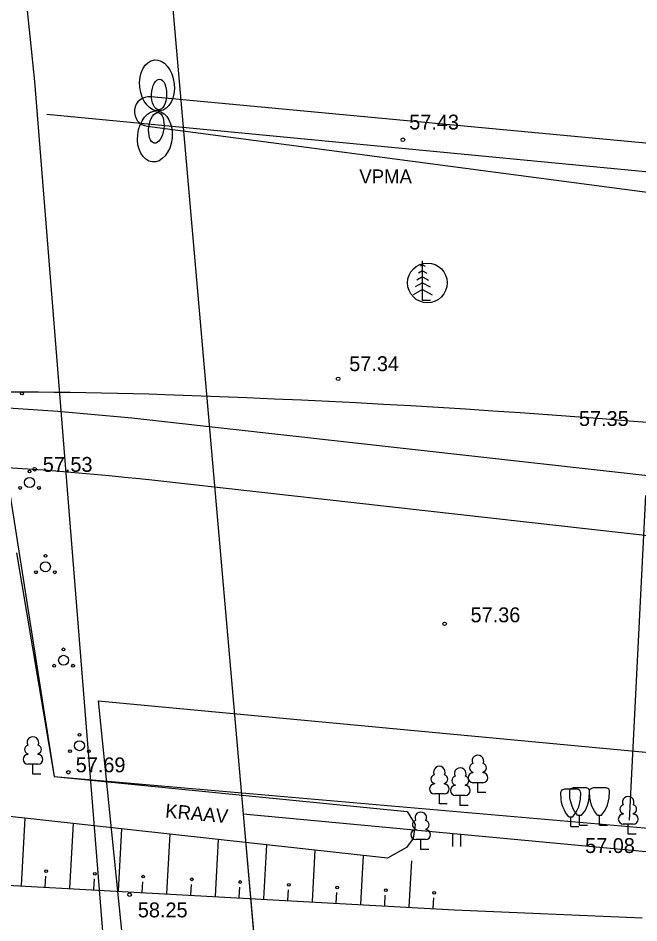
# Model space of a CAD drawing. Extents: x 9156 to 9809, y 2728 to 4000.
# Drawn here: x 9316.8 to 9348.14, y 3691.69 to 3737.31 of the extents above; entities that cross this region are included whole.
import ezdxf

# ---------------------------------------------------------------- set-up
doc = ezdxf.new("R2010")
doc.units = 0
for name, color, linetype in [('Level 1', 7, 'Continuous'), ('Level 11', 7, 'Continuous'), ('Level 16', 7, 'Continuous'), ('Level 17', 7, 'Continuous'), ('Level 18', 7, 'Continuous'), ('Level 21', 7, 'Continuous'), ('Level 54', 7, 'Continuous'), ('Level 56', 7, 'Continuous'), ('Level 6', 7, 'Continuous'), ('Level 7', 7, 'Continuous'), ('Level 8', 7, 'Continuous')]:
    doc.layers.add(name, color=color, linetype=linetype)

msp = doc.modelspace()

# ---------------------------------------------------------------- linework, layer by layer
at = {"layer": 'Level 1'}
for p, q in [((9317.65, 3734.12), (9308.72, 3821.62)), ((9317.65, 3734.12), (9308.72, 3821.62)), ((9347.38, 3362.85), (9317.65, 3734.12)), ((9347.38, 3362.85), (9317.65, 3734.12))]:
    msp.add_line(p, q, dxfattribs=at)
at = {"layer": 'Level 11'}
for points in [[(9328.17, 3697.177), (9337.927, 3586.83), (9359.389, 3586.857), (9356.831, 3657.924), (9386.375, 3658.386), (9385.932, 3691.773)], [(9328.17, 3697.177), (9337.927, 3586.771), (9359.389, 3586.857), (9356.831, 3657.924), (9386.375, 3658.386), (9385.932, 3691.773)]]:
    msp.add_lwpolyline(points, close=True, dxfattribs=at)
at = {"layer": 'Level 16'}
msp.add_line((9318.263, 3732.461), (9362.512, 3728.231), dxfattribs=at)
at = {"layer": 'Level 17'}
for p, q in [((9403.99, 3708.025), (9324.042, 3716.972)), ((9430.183, 3702.075), (9323.709, 3713.991))]:
    msp.add_line(p, q, dxfattribs=at)
for radius, end in [(153, 92.61532), (150, 93.06688)]:
    msp.add_arc((9307.025, 3564.922), radius, 83.61424, end, dxfattribs=at)
at = {"layer": 'Level 18'}
for p, q in [((9486.214, 3718.077), (9323.495, 3733.347)), ((9323.327, 3731.857), (9363.168, 3726.601))]:
    msp.add_line(p, q, dxfattribs=at)
for centre, radius, start, end in [((9323.425, 3732.6), 0.75, 84.6388, 262.4851), ((9316.067, 3469.7), 248.75, 88.12497, 94.00034), ((9307.887, 3219.834), 498.75, 83.04692, 88.12497)]:
    msp.add_arc(centre, radius, start, end, dxfattribs=at)
at = {"layer": 'Level 21'}
msp.add_circle((9337.461, 3723.96), 1, dxfattribs=at)
at = {"layer": 'Level 54'}
for p, q in [((9312.645, 3737.011), (9318.631, 3699.076)), ((9337.219, 3724.87), (9337.093, 3724.8)), ((9337.219, 3723.07), (9337.219, 3725.07)), ((9337.219, 3724.87), (9337.345, 3724.8)), ((9337.219, 3724.27), (9336.921, 3724.105)), ((9337.219, 3724.57), (9337.007, 3724.453)), ((9337.219, 3724.57), (9337.431, 3724.453)), ((9337.219, 3724.27), (9337.517, 3724.105)), ((9337.219, 3723.97), (9336.835, 3723.757)), ((9337.219, 3723.97), (9337.603, 3723.757)), ((9337.219, 3723.62), (9336.743, 3723.356)), ((9337.219, 3723.62), (9337.694, 3723.356)), ((9337.619, 3723.07), (9337.219, 3723.07)), ((9347.659, 3696.87), (9348.477, 3713.238)), ((9316.73, 3710.352), (9318.631, 3699.076)), ((9317.304, 3700.219), (9317.304, 3700.187)), ((9317.804, 3700.219), (9317.804, 3700.187)), ((9317.804, 3699.687), (9317.304, 3699.687)), ((9317.554, 3699.187), (9317.554, 3699.687)), ((9317.954, 3699.187), (9317.554, 3699.187)), ((9339.762, 3699.291), (9339.762, 3699.259)), ((9340.262, 3699.291), (9340.262, 3699.259)), ((9318.631, 3699.076), (9336.447, 3697.307)), ((9318.631, 3699.076), (9385.668, 3693.253)), ((9337.813, 3698.726), (9337.813, 3698.694)), ((9338.313, 3698.726), (9338.313, 3698.694)), ((9338.87, 3698.648), (9338.87, 3698.616)), ((9339.37, 3698.648), (9339.37, 3698.616)), ((9340.262, 3698.759), (9339.762, 3698.759)), ((9340.012, 3698.259), (9340.012, 3698.759)), ((9338.313, 3698.194), (9337.813, 3698.194)), ((9338.063, 3697.694), (9338.063, 3698.194)), ((9340.412, 3698.259), (9340.012, 3698.259)), ((9344.396, 3698.444), (9344.996, 3698.444)), ((9344.842, 3698.518), (9345.442, 3698.518)), ((9345.846, 3698.518), (9346.446, 3698.518)), ((9339.37, 3698.116), (9338.87, 3698.116)), ((9339.12, 3697.616), (9339.12, 3698.116)), ((9335.451, 3694.95), (9314.021, 3697.322)), ((9336.447, 3697.307), (9336.851, 3696.646)), ((9338.463, 3697.694), (9338.063, 3697.694)), ((9339.52, 3697.616), (9339.12, 3697.616)), ((9317.141, 3696.977), (9316.953, 3693.583)), ((9344.596, 3697.044), (9344.796, 3697.044)), ((9344.696, 3696.544), (9344.696, 3697.044)), ((9345.042, 3697.118), (9345.242, 3697.118)), ((9345.142, 3696.618), (9345.142, 3697.118)), ((9346.046, 3697.118), (9346.246, 3697.118)), ((9346.146, 3696.618), (9346.146, 3697.118)), ((9347.346, 3697.203), (9347.346, 3697.171)), ((9347.846, 3697.203), (9347.846, 3697.171)), ((9319.581, 3696.707), (9319.4, 3693.447)), ((9322.021, 3696.437), (9321.848, 3693.311)), ((9336.851, 3696.646), (9336.74, 3695.938)), ((9336.875, 3696.421), (9336.875, 3696.389)), ((9337.375, 3696.421), (9337.375, 3696.389)), ((9344.696, 3696.544), (9345.096, 3696.544)), ((9345.142, 3696.618), (9345.542, 3696.618)), ((9346.146, 3696.618), (9346.546, 3696.618)), ((9347.846, 3696.671), (9347.346, 3696.671)), ((9347.596, 3696.171), (9347.596, 3696.671)), ((9324.461, 3696.167), (9324.295, 3693.175)), ((9336.74, 3695.938), (9336.405, 3695.491)), ((9338.729, 3696.163), (9338.729, 3695.543)), ((9339.135, 3696.152), (9339.135, 3695.543)), ((9347.996, 3696.171), (9347.596, 3696.171)), ((9326.901, 3695.897), (9326.742, 3693.039)), ((9329.341, 3695.626), (9329.19, 3692.904)), ((9336.405, 3695.491), (9335.451, 3694.95)), ((9337.375, 3695.889), (9336.875, 3695.889)), ((9337.125, 3695.389), (9337.125, 3695.889)), ((9331.781, 3695.356), (9331.637, 3692.768)), ((9334.221, 3695.086), (9334.084, 3692.632)), ((9337.525, 3695.389), (9337.125, 3695.389)), ((9336.661, 3694.816), (9336.532, 3692.496)), ((9318.177, 3693.515), (9318.206, 3694.04)), ((9320.624, 3693.379), (9320.653, 3693.904)), ((9323.071, 3693.243), (9323.1, 3693.768)), ((9325.519, 3693.107), (9325.548, 3693.632)), ((9327.966, 3692.971), (9327.995, 3693.496)), ((9330.413, 3692.836), (9330.443, 3693.361)), ((9332.861, 3692.7), (9332.89, 3693.225)), ((9335.308, 3692.564), (9335.337, 3693.089)), ((9337.756, 3692.428), (9337.785, 3692.953)), ((9338.834, 3692.345), (9348.3, 3691.946))]:
    msp.add_line(p, q, dxfattribs=at)
for points in [[(9295.071, 3750), (9300.327, 3695.705), (9300.595, 3694.735), (9301.563, 3694.411), (9315.023, 3693.667), (9338.834, 3692.345)], [(9344.596, 3697.044), (9344.438, 3697.256), (9344.373, 3697.368), (9344.296, 3697.544), (9344.235, 3697.769), (9344.211, 3697.925), (9344.196, 3698.244), (9344.198, 3698.285), (9344.228, 3698.357), (9344.268, 3698.394), (9344.396, 3698.444)], [(9345.042, 3697.118), (9344.884, 3697.331), (9344.819, 3697.443), (9344.742, 3697.618), (9344.681, 3697.843), (9344.657, 3697.999), (9344.642, 3698.318), (9344.644, 3698.36), (9344.674, 3698.431), (9344.714, 3698.468), (9344.842, 3698.518)], [(9344.796, 3697.044), (9344.955, 3697.256), (9345.019, 3697.368), (9345.096, 3697.544), (9345.157, 3697.769), (9345.181, 3697.925), (9345.196, 3698.244), (9345.194, 3698.285), (9345.165, 3698.357), (9345.124, 3698.394), (9344.996, 3698.444)], [(9345.242, 3697.118), (9345.401, 3697.331), (9345.465, 3697.443), (9345.542, 3697.618), (9345.604, 3697.843), (9345.627, 3697.999), (9345.642, 3698.318), (9345.64, 3698.36), (9345.611, 3698.431), (9345.57, 3698.468), (9345.442, 3698.518)], [(9346.046, 3697.118), (9345.888, 3697.331), (9345.823, 3697.443), (9345.746, 3697.618), (9345.685, 3697.843), (9345.661, 3697.999), (9345.646, 3698.318), (9345.648, 3698.36), (9345.678, 3698.431), (9345.718, 3698.468), (9345.846, 3698.518)], [(9346.246, 3697.118), (9346.405, 3697.331), (9346.469, 3697.443), (9346.546, 3697.618), (9346.607, 3697.843), (9346.631, 3697.999), (9346.646, 3698.318), (9346.644, 3698.36), (9346.615, 3698.431), (9346.574, 3698.468), (9346.446, 3698.518)]]:
    msp.add_lwpolyline(points, dxfattribs=at)
for centre, radius in [((9336.225, 3731.179), 0.0909), ((9332.955, 3719.124), 0.0909), ((9316.999, 3718.389), 0.0707), ((9317.638, 3714.563), 0.0909), ((9317.382, 3714.446), 0.0707), ((9317.382, 3713.896), 0.25), ((9316.906, 3713.621), 0.0707), ((9317.858, 3713.621), 0.0707), ((9318.184, 3710.194), 0.0707), ((9318.184, 3709.644), 0.25), ((9317.708, 3709.369), 0.0707), ((9318.66, 3709.369), 0.0707), ((9338.332, 3706.771), 0.0909), ((9319.1, 3705.483), 0.0707), ((9319.1, 3704.933), 0.25), ((9318.624, 3704.658), 0.0707), ((9319.577, 3704.658), 0.0707), ((9319.902, 3701.174), 0.0707), ((9319.902, 3700.624), 0.25), ((9319.426, 3700.349), 0.0707), ((9320.379, 3700.349), 0.0707), ((9319.339, 3699.284), 0.0909), ((9318.227, 3694.295), 0.0683), ((9320.675, 3694.159), 0.0683), ((9323.122, 3694.023), 0.0683), ((9325.569, 3693.887), 0.0683), ((9328.017, 3693.751), 0.0683), ((9330.464, 3693.615), 0.0683), ((9322.429, 3693.113), 0.0909), ((9332.912, 3693.479), 0.0683), ((9335.359, 3693.344), 0.0683), ((9337.806, 3693.208), 0.0683)]:
    msp.add_circle(centre, radius, dxfattribs=at)
for centre, radius, start, end in [((9317.554, 3700.787), 0.292, 332.5799, 207.4201), ((9317.354, 3700.437), 0.224, 105.2441, 257.079), ((9317.754, 3700.437), 0.224, 282.921, 74.7559), ((9317.304, 3699.937), 0.25, 90, 270), ((9317.804, 3699.937), 0.25, 270, 90), ((9340.012, 3699.859), 0.292, 332.5799, 207.4201), ((9338.063, 3699.294), 0.292, 332.5799, 207.4201), ((9339.812, 3699.509), 0.224, 105.2441, 257.079), ((9340.212, 3699.509), 0.224, 282.921, 74.7559), ((9337.863, 3698.944), 0.224, 105.2441, 257.079), ((9338.263, 3698.944), 0.224, 282.921, 74.7559), ((9339.12, 3699.216), 0.292, 332.5799, 207.4201), ((9339.762, 3699.009), 0.25, 90, 270), ((9340.262, 3699.009), 0.25, 270, 90), ((9337.813, 3698.444), 0.25, 90, 270), ((9338.313, 3698.444), 0.25, 270, 90), ((9338.92, 3698.866), 0.224, 105.2441, 257.079), ((9339.32, 3698.866), 0.224, 282.921, 74.7559), ((9338.87, 3698.366), 0.25, 90, 270), ((9339.37, 3698.366), 0.25, 270, 90), ((9347.596, 3697.771), 0.292, 332.5799, 207.4201), ((9337.125, 3696.989), 0.292, 332.5799, 207.4201), ((9347.396, 3697.421), 0.224, 105.2441, 257.079), ((9347.796, 3697.421), 0.224, 282.921, 74.7559), ((9336.925, 3696.639), 0.224, 105.2441, 257.079), ((9337.325, 3696.639), 0.224, 282.921, 74.7559), ((9347.346, 3696.921), 0.25, 90, 270), ((9347.846, 3696.921), 0.25, 270, 90), ((9336.875, 3696.139), 0.25, 90, 270), ((9337.375, 3696.139), 0.25, 270, 90)]:
    msp.add_arc(centre, radius, start, end, dxfattribs=at)
at = {"layer": 'Level 56'}
for p, q in [((9486.214, 3718.077), (9323.495, 3733.347)), ((9323.327, 3731.857), (9363.168, 3726.601)), ((9403.99, 3708.025), (9324.042, 3716.972)), ((9430.183, 3702.075), (9323.709, 3713.991))]:
    msp.add_line(p, q, dxfattribs=at)
for centre, radius, start, end in [((9323.425, 3732.6), 0.75, 84.6388, 262.4851), ((9316.067, 3469.7), 248.75, 88.12497, 94.00034), ((9307.887, 3219.834), 498.75, 83.04692, 88.12497), ((9307.025, 3564.922), 153, 83.61424, 92.61532), ((9307.025, 3564.922), 150, 83.61424, 93.06688)]:
    msp.add_arc(centre, radius, start, end, dxfattribs=at)
at = {"layer": 'Level 6'}
msp.add_line((9306.372, 3945.862), (9356.727, 3371.389), dxfattribs=at)
at = {"layer": 'Level 7'}
for q in [(9322.45, 3687.11), (9474.788, 3688.481)]:
    msp.add_line((9320.839, 3702.885), q, dxfattribs=at)
at = {"layer": 'Level 8'}
for centre, major_axis, ratio in [((9323.814, 3733.915), (0.134, -1.286), 0.674652), ((9323.814, 3733.915), (0.134, -1.286), 0.674652), ((9323.814, 3733.915), (0.134, -1.286), 0.674652), ((9323.814, 3733.915), (0.134, -1.286), 0.674652), ((9323.921, 3733.46), (-0.027, -0.777), 0.486914), ((9323.921, 3733.46), (-0.027, -0.777), 0.486914), ((9323.921, 3733.46), (-0.027, -0.777), 0.486914), ((9323.921, 3733.46), (-0.027, -0.777), 0.486914), ((9323.707, 3731.343), (0.134, 1.286), 0.674652), ((9323.707, 3731.343), (0.134, 1.286), 0.674652), ((9323.707, 3731.343), (0.134, 1.286), 0.674652), ((9323.707, 3731.343), (0.134, 1.286), 0.674652), ((9323.78, 3731.779), (0.102, 0.771), 0.486914), ((9323.78, 3731.779), (0.102, 0.771), 0.486914), ((9323.78, 3731.779), (0.102, 0.771), 0.486914), ((9323.78, 3731.779), (0.102, 0.771), 0.486914)]:
    msp.add_ellipse(centre, major_axis=major_axis, ratio=ratio, dxfattribs=at)

# ---------------------------------------------------------------- texts
at = {"layer": 'Level 54'}
for s, height, p in [('57.43', 0.75, (9336.545, 3731.695)), ('VPMA', 0.7, (9334.026, 3728.979)), ('57.34', 0.75, (9333.517, 3719.512)), ('57.35', 0.75, (9345.109, 3716.747)), ('57.53', 0.75, (9318.05, 3714.432)), ('57.36', 0.75, (9339.64, 3706.849)), ('57.69', 0.75, (9319.713, 3699.284)), ('57.08', 0.75, (9345.421, 3695.214)), ('58.25', 0.75, (9322.848, 3691.969))]:
    msp.add_text(s, height=height, dxfattribs=at).set_placement(p)
msp.add_text('KRAAV', height=0.7, rotation=354.6169, dxfattribs=at).set_placement((9324.209, 3697.008))

doc.saveas('drawing.dxf')
